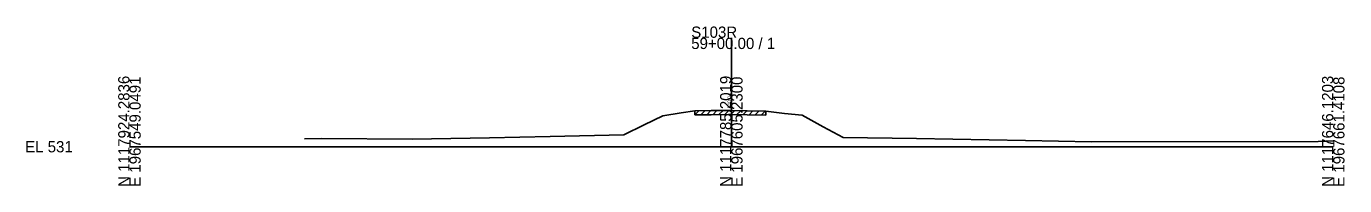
# Model space of a CAD drawing. Extents: x 974 to 1303, y 990 to 10019.
# Drawn here: x 974.3 to 1302.8, y 1990.3 to 2030 of the extents above; entities that cross this region are included whole.
import ezdxf

# ---------------------------------------------------------------- set-up
doc = ezdxf.new("R2010")
doc.units = 0
for name, color, linetype in [('Level 10', 7, 'Continuous'), ('Level 60', 7, 'Continuous'), ('Level 61', 7, 'Continuous'), ('Level 63', 7, 'Continuous')]:
    doc.layers.add(name, color=color, linetype=linetype)

msp = doc.modelspace()

# ---------------------------------------------------------------- linework, layer by layer
at = {"layer": 'Level 60'}
for p, q in [((1128.26, 2005.45), (1132.92, 2007.73)), ((1132.92, 2007.73), (1137.49, 2008.44)), ((1137.49, 2008.44), (1140.9, 2008.93)), ((1140.9, 2008.93), (1144.95, 2008.99)), ((1144.95, 2008.99), (1149.28, 2009.05)), ((1149.28, 2009.05), (1150, 2009.04)), ((1150, 2009.04), (1153.95, 2008.95)), ((1153.95, 2008.95), (1158.61, 2008.87)), ((1158.61, 2008.87), (1163.26, 2008.31)), ((1163.26, 2008.31), (1167.63, 2007.85)), ((1167.63, 2007.85), (1172.89, 2005)), ((1123.2, 2002.97), (1128.26, 2005.45)), ((1172.89, 2005), (1177.85, 2002.31)), ((1043.66, 2001.97), (1047.94, 2002.06)), ((1047.94, 2002.06), (1070.46, 2001.89)), ((1070.46, 2001.89), (1089.76, 2002.22)), ((1089.76, 2002.22), (1104.88, 2002.56)), ((1104.88, 2002.56), (1123.2, 2002.97)), ((1177.85, 2002.31), (1196.16, 2002.09)), ((1196.16, 2002.09), (1223.28, 2001.54)), ((1223.28, 2001.54), (1239.73, 2001.25)), ((1239.73, 2001.25), (1296.25, 2001.34)), ((1296.25, 2001.34), (1300, 2001.49))]:
    msp.add_line(p, q, dxfattribs=at)
at = {"layer": 'Level 61'}
for p, q in [((1140.9, 2007.93), (1141.92, 2008.94)), ((1140.9, 2007.93), (1140.9, 2008.93)), ((1140.9, 2007.93), (1144.95, 2007.99)), ((1140.9, 2007.93), (1140.9, 2007.93)), ((1142.4, 2007.95), (1143.42, 2008.97)), ((1143.9, 2007.97), (1144.92, 2008.99)), ((1144.95, 2007.99), (1149.28, 2008.05)), ((1145.4, 2007.99), (1146.42, 2009.01)), ((1146.9, 2008.02), (1147.92, 2009.03)), ((1148.4, 2008.04), (1149.41, 2009.05)), ((1149.28, 2008.05), (1150, 2008.04)), ((1149.9, 2008.04), (1150.88, 2009.02)), ((1150, 2008.04), (1153.95, 2007.95)), ((1151.4, 2008), (1152.38, 2008.98)), ((1152.9, 2007.97), (1153.88, 2008.95)), ((1153.95, 2007.95), (1158.61, 2007.87)), ((1154.4, 2007.94), (1155.39, 2008.92)), ((1155.9, 2007.91), (1156.89, 2008.9)), ((1157.4, 2007.89), (1158.39, 2008.87)), ((1158.61, 2008.87), (1158.61, 2007.87))]:
    msp.add_line(p, q, dxfattribs=at)
at = {"layer": 'Level 63'}
for p, q in [((1150, 2000), (1150, 2027.15)), ((1000, 2000), (1150, 2000)), ((1150, 2000), (1300, 2000))]:
    msp.add_line(p, q, dxfattribs=at)

# ---------------------------------------------------------------- texts
at = {"layer": 'Level 10'}
msp.add_text('540.04', height=0.9, rotation=90, dxfattribs=at).set_placement((1149.95, 2009.54))
at = {"layer": 'Level 63'}
for s, p in [('59+00.00 / 1', (1140, 2024.35)), ('S103R', (1140, 2027.15)), ('EL 531', (974, 1998.6))]:
    msp.add_text(s, height=2.8, dxfattribs=at).set_placement(p)
for s, p in [('N 1117924.2836', (1000, 1990)), ('E 1967549.0491', (1002.8, 1990)), ('N 1117785.2019', (1150, 1990)), ('E 1967605.2300', (1152.8, 1990)), ('N 1117646.1203', (1300, 1990)), ('E 1967661.4108', (1302.8, 1990))]:
    msp.add_text(s, height=2.8, rotation=90, dxfattribs=at).set_placement(p)

doc.saveas('drawing.dxf')
